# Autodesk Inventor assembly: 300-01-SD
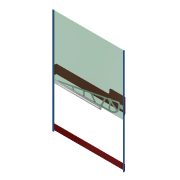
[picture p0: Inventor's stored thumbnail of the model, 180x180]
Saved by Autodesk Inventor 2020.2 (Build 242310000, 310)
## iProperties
Created: 2014-10
Part Number: 300-01-SD
Document SubType Name: Assembly
Designer: F.Stasiak
Catalog Web Link: www.expertbooks.pl
Manager: www.cadconsulting.pl
Company: Fabian Stasiak CAD Consulting
Author: F.Stasiak
Subject: Zbiór ćwiczeń. Autodesk Inventor 2020. Kurs Professional
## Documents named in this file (7)
- C:\2020_Kurs_Professional\R3 Dynamika\300-01-SD.iam
- C:\2020_Kurs_Professional\R3 Dynamika\Komponenty_dyn\300-01-01.ipt
- C:\2020_Kurs_Professional\R3 Dynamika\Komponenty_dyn\300-01-02.ipt
- C:\2020_Kurs_Professional\R3 Dynamika\Komponenty_dyn\300-01-03.ipt
- C:\2020_Kurs_Professional\R3 Dynamika\Komponenty_dyn\300-01-05.ipt
- C:\2020_Kurs_Professional\R3 Dynamika\300-01-SD\Design Accelerator\Przekładnie walcowe1.iam
- C:\2020_Kurs_Professional\R3 Dynamika\Komponenty_dyn\300-01-06.ipt
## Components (7 placed, 6 different names)
1. 300-01-02:1 — Zestawiający:1, Zestawiający:2, Równoległy:1, Równoległy:2, Równoległy:4, Zestawiający:10, Równoległy:6, Zestawiający:11, Równoległy:8, Równoległy:9, Równoległy:10
2. 300-01-01:1 — Zestawiający:1, Zestawiający:2, Zestawiający:3, Zestawiający:4, Zestawiający:5, Równoległy:4
3. 300-01-02:2 — Zestawiający:3, Równoległy:1, Równoległy:2, Zestawiający:12
4. 300-01-03:1 — Zestawiający:4, Zestawiający:5, Zestawiający:12, Styczny:1
5. 300-01-05:1 — Kąt:2, Zestawiający:10, Równoległy:6, Zestawiający:11, Wstaw:1, Wstaw:2, OBRÓT
6. Przekładnie walcowe:1 [sub-assembly] — Kąt:2, Wstaw:1, OBRÓT, Wstaw:2, Styczny:1
7. 300-01-06:1 — Równoległy:8, Równoległy:9, Równoległy:10
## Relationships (20: Mate 8, Flush 7, Angle 2, Insert 2, Tangent 1)
- OBRÓT [Angle]: 300-01-05:1 ↔ Przekładnie walcowe:1
- Zestawiający:1 [Mate]: 300-01-02:1 ↔ 300-01-01:1
- Zestawiający:2 [Mate]: 300-01-02:1 ↔ 300-01-01:1
- Zestawiający:3 [Mate]: 300-01-01:1 ↔ 300-01-02:2
- Równoległy:1 [Flush]: 300-01-02:1 ↔ 300-01-02:2
- Równoległy:2 [Flush]: 300-01-02:1 ↔ 300-01-02:2
- Zestawiający:4 [Mate]: 300-01-01:1 ↔ 300-01-03:1
- Zestawiający:5 [Mate]: 300-01-01:1 ↔ 300-01-03:1
- Równoległy:4 [Flush]: 300-01-02:1 ↔ 300-01-01:1
- Kąt:2 [Angle]: 300-01-05:1 ↔ Przekładnie walcowe:1
- Zestawiający:10 [Mate]: 300-01-02:1 ↔ 300-01-05:1
- Równoległy:6 [Flush]: 300-01-02:1 ↔ 300-01-05:1
- Zestawiający:11 [Mate]: 300-01-02:1 ↔ 300-01-05:1
- Wstaw:1 [Insert]: 300-01-05:1 ↔ Przekładnie walcowe:1
- Wstaw:2 [Insert]: 300-01-05:1 ↔ Przekładnie walcowe:1
- Zestawiający:12 [Mate]: 300-01-02:2 ↔ 300-01-03:1
- Styczny:1 [Tangent]: 300-01-03:1 ↔ Przekładnie walcowe:1
- Równoległy:8 [Flush]: 300-01-02:1 ↔ 300-01-06:1
- Równoległy:9 [Flush]: 300-01-02:1 ↔ 300-01-06:1
- Równoległy:10 [Flush]: 300-01-02:1 ↔ 300-01-06:1
